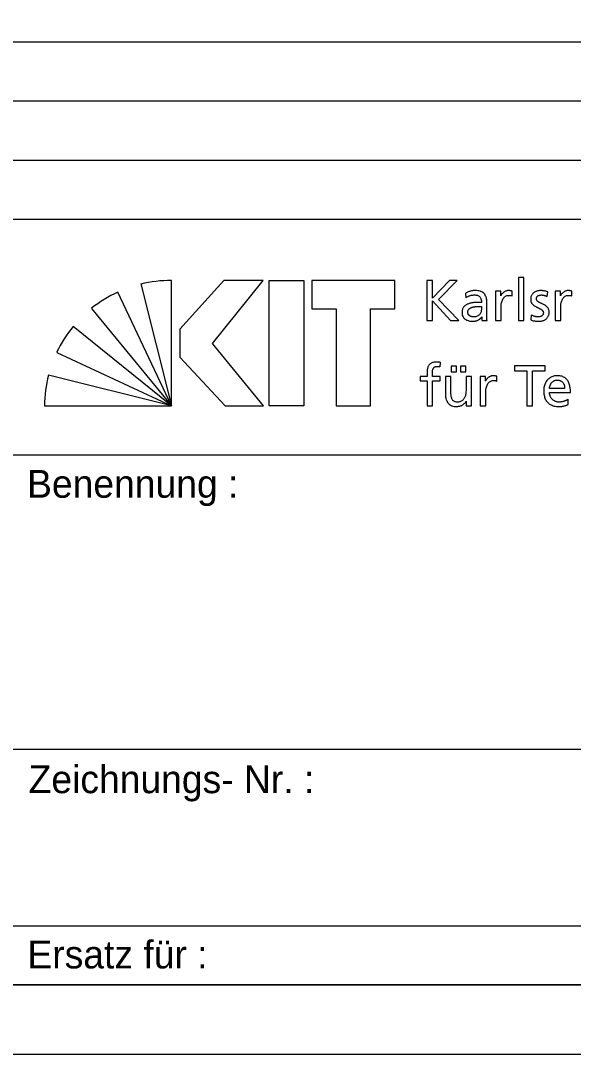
# Model space of a CAD drawing. Extents: x 0 to 168, y 0 to 119.
# Drawn here: x 150.53 to 158.47, y 0 to 14.85 of the extents above; entities that cross this region are included whole.
import ezdxf

# ---------------------------------------------------------------- set-up
doc = ezdxf.new("R2010")
doc.units = 0
doc.layers.add('90_Plankopf', color=7, linetype='Continuous')

msp = doc.modelspace()

# ---------------------------------------------------------------- linework, layer by layer
at = {"layer": '90_Plankopf'}
for p, q in [((131.624, 14.548), (167.2, 14.548)), ((131.624, 13.698), (167.2, 13.698)), ((131.624, 12.848), (167.2, 12.848)), ((131.624, 11.998), (167.2, 11.998)), ((131.624, 11.998), (167.2, 11.998)), ((152.255, 11.067), (152.696, 9.317)), ((152.696, 9.317), (152.696, 11.117)), ((156.362, 11.117), (156.362, 10.541)), ((152.696, 9.317), (151.927, 10.95)), ((156.916, 10.932), (156.92, 10.866)), ((157.585, 10.897), (157.585, 10.966)), ((158.091, 10.888), (158.098, 10.956)), ((158.442, 10.897), (158.442, 10.966)), ((151.549, 10.717), (152.696, 9.317)), ((157.146, 10.742), (157.146, 10.705)), ((157.224, 10.624), (157.224, 10.798)), ((157.859, 10.624), (157.855, 10.554)), ((152.696, 9.317), (151.287, 10.457)), ((156.362, 10.541), (156.444, 10.541)), ((156.701, 10.541), (156.822, 10.541)), ((151.048, 10.083), (152.696, 9.317)), ((156.555, 9.879), (156.558, 9.941)), ((152.696, 9.317), (150.932, 9.758)), ((157.365, 9.673), (157.365, 9.742)), ((158.341, 9.568), (158.123, 9.568)), ((158.123, 9.51), (158.424, 9.51)), ((158.392, 9.335), (158.392, 9.412)), ((150.873, 9.317), (152.696, 9.317)), ((150.4, 8.614), (167.2, 8.614)), ((150.4, 4.384), (167.2, 4.384)), ((150.4, 1.846), (167.2, 1.846)), ((167.2, 1), (131.624, 1)), ((133.96, 1), (167.2, 1)), ((133.96, 1), (167.2, 1))]:
    msp.add_line(p, q, dxfattribs=at)
for points in [[(0, 0), (168.2, 0), (168.2, 118.8), (0, 118.8)], [(5, 117.8), (167.2, 117.8), (167.2, 1), (5, 1)], [(154.013, 11.117), (153.447, 11.117), (152.815, 10.42), (152.815, 10.018), (153.468, 9.317), (154.017, 9.317), (153.284, 10.213)], [(154.594, 11.117), (154.594, 9.317), (154.1, 9.317), (154.1, 11.117)], [(154.712, 11.117), (154.712, 10.712), (155.06, 10.712), (155.06, 9.317), (155.554, 9.317), (155.554, 10.712), (155.902, 10.712), (155.902, 11.117)]]:
    msp.add_lwpolyline(points, close=True, dxfattribs=at)
for points in [[(157.676, 10.541), (157.754, 10.541), (157.754, 11.16), (157.676, 11.16), (157.676, 10.541)], [(156.822, 10.541), (156.529, 10.845), (156.8, 11.117), (156.69, 11.117), (156.444, 10.864), (156.444, 11.117), (156.362, 11.117)], [(157.424, 10.897), (157.423, 10.897), (157.423, 10.962), (157.35, 10.962), (157.35, 10.541), (157.428, 10.541), (157.428, 10.733)], [(158.281, 10.897), (158.28, 10.897), (158.28, 10.962), (158.207, 10.962), (158.207, 10.541), (158.285, 10.541), (158.285, 10.733)], [(156.444, 10.541), (156.444, 10.823), (156.701, 10.541)], [(157.153, 10.596), (157.154, 10.596), (157.154, 10.541), (157.227, 10.541)], [(156.711, 9.885), (156.711, 9.803), (156.788, 9.803), (156.788, 9.885), (156.711, 9.885)], [(156.846, 9.885), (156.846, 9.803), (156.924, 9.803), (156.924, 9.885), (156.846, 9.885)], [(157.798, 9.317), (157.881, 9.317), (157.881, 9.821), (158.06, 9.821), (158.06, 9.893), (157.619, 9.893), (157.619, 9.821), (157.798, 9.821), (157.798, 9.317)], [(156.365, 9.777), (156.365, 9.738), (156.266, 9.738), (156.266, 9.676), (156.365, 9.676), (156.365, 9.317), (156.442, 9.317), (156.442, 9.676), (156.554, 9.676), (156.554, 9.738), (156.442, 9.738), (156.442, 9.784)], [(156.708, 9.52), (156.708, 9.738), (156.631, 9.738), (156.631, 9.488)], [(157.003, 9.317), (157.003, 9.738), (156.925, 9.738), (156.925, 9.543)], [(157.204, 9.673), (157.203, 9.673), (157.203, 9.738), (157.13, 9.738), (157.13, 9.317), (157.208, 9.317), (157.208, 9.509)], [(156.926, 9.384), (156.928, 9.384), (156.928, 9.317), (157.003, 9.317)]]:
    msp.add_lwpolyline(points, dxfattribs=at)
for centre, start, end in [((152.69, 9.211), 89.8053, 103.1895), ((152.732, 9.224), 115.0126, 128.3968), ((152.763, 9.253), 140.7898, 154.174), ((152.778, 9.288), 165.7222, 179.1064)]:
    msp.add_arc(centre, 1.906, start, end, dxfattribs=at)
for points in [[(157.224, 10.798), (157.224, 10.836), (157.218, 10.868), (157.207, 10.894), (157.195, 10.92), (157.177, 10.939), (157.152, 10.952), (157.127, 10.965), (157.094, 10.972), (157.054, 10.972), (157.028, 10.972), (157.003, 10.968), (156.98, 10.961), (156.956, 10.954), (156.935, 10.944), (156.916, 10.932)], [(156.92, 10.866), (156.931, 10.875), (156.943, 10.883), (156.956, 10.889), (156.969, 10.896), (156.983, 10.901), (156.998, 10.904), (157.013, 10.908), (157.027, 10.909), (157.042, 10.909), (157.068, 10.909), (157.088, 10.905), (157.104, 10.897), (157.119, 10.889), (157.13, 10.877), (157.136, 10.86), (157.143, 10.844), (157.146, 10.824), (157.146, 10.799)], [(157.585, 10.966), (157.58, 10.967), (157.575, 10.968), (157.57, 10.969), (157.565, 10.97), (157.56, 10.971), (157.554, 10.971), (157.548, 10.972), (157.542, 10.972), (157.534, 10.972), (157.519, 10.972), (157.505, 10.969), (157.49, 10.962), (157.476, 10.956), (157.464, 10.947), (157.452, 10.936), (157.441, 10.925), (157.431, 10.912), (157.424, 10.897)], [(157.428, 10.733), (157.428, 10.768), (157.433, 10.799), (157.442, 10.824), (157.451, 10.85), (157.465, 10.87), (157.482, 10.883), (157.499, 10.897), (157.519, 10.904), (157.542, 10.904), (157.549, 10.904), (157.556, 10.904), (157.564, 10.903), (157.571, 10.902), (157.578, 10.9), (157.585, 10.897)], [(158.098, 10.956), (158.083, 10.96), (158.067, 10.964), (158.052, 10.967), (158.036, 10.97), (158.019, 10.972), (158.001, 10.972), (157.981, 10.972), (157.961, 10.969), (157.943, 10.964), (157.925, 10.959), (157.909, 10.951), (157.896, 10.94), (157.882, 10.929), (157.872, 10.916), (157.864, 10.9), (157.857, 10.883), (157.853, 10.864), (157.853, 10.842), (157.853, 10.826), (157.856, 10.811), (157.863, 10.799), (157.869, 10.787), (157.878, 10.776), (157.889, 10.767), (157.9, 10.758), (157.912, 10.75), (157.925, 10.743), (157.938, 10.736), (157.951, 10.729), (157.963, 10.723), (157.976, 10.717), (157.988, 10.711), (157.999, 10.704), (158.01, 10.698), (158.019, 10.691), (158.025, 10.683), (158.032, 10.675), (158.035, 10.665), (158.035, 10.654), (158.035, 10.643), (158.033, 10.633), (158.028, 10.626), (158.023, 10.618), (158.017, 10.612), (158.009, 10.607), (158.001, 10.602), (157.993, 10.599), (157.983, 10.597), (157.974, 10.595), (157.965, 10.594), (157.956, 10.594), (157.948, 10.594), (157.939, 10.595), (157.928, 10.597), (157.917, 10.599), (157.905, 10.603), (157.893, 10.607), (157.881, 10.612), (157.87, 10.617), (157.859, 10.624)], [(157.855, 10.554), (157.873, 10.545), (157.892, 10.539), (157.912, 10.536), (157.931, 10.532), (157.951, 10.531), (157.971, 10.531), (157.99, 10.531), (158.008, 10.534), (158.025, 10.539), (158.043, 10.544), (158.059, 10.552), (158.073, 10.563), (158.086, 10.574), (158.097, 10.588), (158.105, 10.604), (158.114, 10.621), (158.118, 10.64), (158.118, 10.662), (158.118, 10.682), (158.114, 10.698), (158.108, 10.711), (158.101, 10.724), (158.092, 10.736), (158.082, 10.745), (158.071, 10.754), (158.059, 10.762), (158.046, 10.769), (158.033, 10.776), (158.02, 10.782), (158.007, 10.787), (157.994, 10.793), (157.982, 10.799), (157.972, 10.805), (157.961, 10.812), (157.952, 10.819), (157.945, 10.827), (157.939, 10.836), (157.936, 10.846), (157.935, 10.858), (157.936, 10.87), (157.939, 10.879), (157.946, 10.887), (157.953, 10.894), (157.962, 10.9), (157.973, 10.904), (157.984, 10.908), (157.996, 10.909), (158.01, 10.909), (158.014, 10.909), (158.02, 10.909), (158.028, 10.908), (158.035, 10.906), (158.043, 10.905), (158.051, 10.903), (158.059, 10.901), (158.067, 10.898), (158.074, 10.896), (158.081, 10.893), (158.087, 10.891), (158.091, 10.888)], [(158.442, 10.966), (158.437, 10.967), (158.432, 10.968), (158.427, 10.969), (158.422, 10.97), (158.417, 10.971), (158.411, 10.971), (158.405, 10.972), (158.399, 10.972), (158.391, 10.972), (158.376, 10.972), (158.362, 10.969), (158.347, 10.962), (158.333, 10.956), (158.321, 10.947), (158.309, 10.936), (158.298, 10.925), (158.288, 10.912), (158.281, 10.897)], [(158.285, 10.733), (158.285, 10.768), (158.29, 10.799), (158.299, 10.824), (158.308, 10.85), (158.322, 10.87), (158.339, 10.883), (158.356, 10.897), (158.376, 10.904), (158.399, 10.904), (158.406, 10.904), (158.413, 10.904), (158.421, 10.903), (158.428, 10.902), (158.435, 10.9), (158.442, 10.897)], [(157.146, 10.799), (157.136, 10.8), (157.127, 10.8), (157.118, 10.801), (157.109, 10.801), (157.1, 10.801), (157.092, 10.801), (157.083, 10.801), (157.074, 10.801), (157.064, 10.801), (157.047, 10.801), (157.03, 10.8), (157.013, 10.797), (156.995, 10.794), (156.977, 10.789), (156.96, 10.783), (156.943, 10.776), (156.928, 10.768), (156.914, 10.757), (156.9, 10.746), (156.889, 10.733), (156.881, 10.718), (156.872, 10.702), (156.868, 10.684), (156.868, 10.662), (156.868, 10.632), (156.875, 10.607), (156.888, 10.588), (156.901, 10.568), (156.919, 10.554), (156.942, 10.545), (156.965, 10.536), (156.992, 10.531), (157.022, 10.531), (157.04, 10.531), (157.056, 10.534), (157.07, 10.538), (157.084, 10.542), (157.097, 10.547), (157.107, 10.554), (157.118, 10.56), (157.127, 10.567), (157.135, 10.575), (157.142, 10.582), (157.148, 10.589), (157.153, 10.596)], [(157.146, 10.705), (157.146, 10.684), (157.142, 10.665), (157.133, 10.648), (157.124, 10.631), (157.111, 10.618), (157.093, 10.609), (157.076, 10.599), (157.054, 10.594), (157.029, 10.594), (157.02, 10.594), (157.011, 10.596), (157.002, 10.598), (156.993, 10.601), (156.984, 10.606), (156.976, 10.611), (156.969, 10.617), (156.962, 10.625), (156.958, 10.633), (156.953, 10.641), (156.951, 10.651), (156.95, 10.662), (156.951, 10.677), (156.954, 10.69), (156.962, 10.699), (156.969, 10.709), (156.978, 10.717), (156.99, 10.723), (157.001, 10.729), (157.014, 10.733), (157.027, 10.736), (157.04, 10.739), (157.053, 10.741), (157.065, 10.742), (157.077, 10.743), (157.088, 10.743), (157.097, 10.743), (157.105, 10.743), (157.113, 10.743), (157.121, 10.743), (157.13, 10.742), (157.138, 10.742), (157.146, 10.742)], [(157.227, 10.541), (157.226, 10.545), (157.226, 10.551), (157.225, 10.557), (157.225, 10.564), (157.224, 10.573), (157.224, 10.584), (157.224, 10.595), (157.224, 10.608), (157.224, 10.624)], [(156.558, 9.941), (156.55, 9.942), (156.542, 9.944), (156.534, 9.945), (156.525, 9.946), (156.516, 9.946), (156.506, 9.946), (156.478, 9.946), (156.454, 9.942), (156.436, 9.934), (156.417, 9.926), (156.403, 9.915), (156.392, 9.9), (156.382, 9.885), (156.375, 9.867), (156.371, 9.847), (156.367, 9.826), (156.365, 9.803), (156.365, 9.777)], [(156.442, 9.784), (156.442, 9.798), (156.443, 9.811), (156.445, 9.823), (156.446, 9.835), (156.45, 9.846), (156.455, 9.855), (156.46, 9.864), (156.468, 9.871), (156.478, 9.876), (156.488, 9.881), (156.501, 9.883), (156.518, 9.883), (156.524, 9.883), (156.531, 9.883), (156.538, 9.882), (156.544, 9.881), (156.55, 9.88), (156.555, 9.879)], [(157.365, 9.742), (157.36, 9.743), (157.355, 9.744), (157.35, 9.745), (157.345, 9.746), (157.34, 9.747), (157.334, 9.747), (157.328, 9.748), (157.322, 9.748), (157.314, 9.748), (157.299, 9.748), (157.285, 9.745), (157.27, 9.738), (157.256, 9.732), (157.244, 9.723), (157.232, 9.712), (157.221, 9.701), (157.211, 9.688), (157.204, 9.673)], [(157.208, 9.509), (157.208, 9.544), (157.213, 9.575), (157.222, 9.6), (157.232, 9.626), (157.245, 9.646), (157.262, 9.659), (157.279, 9.673), (157.299, 9.68), (157.322, 9.68), (157.329, 9.681), (157.336, 9.68), (157.344, 9.679), (157.351, 9.678), (157.358, 9.676), (157.365, 9.673)], [(158.424, 9.51), (158.424, 9.544), (158.421, 9.576), (158.414, 9.605), (158.408, 9.634), (158.398, 9.659), (158.384, 9.68), (158.369, 9.701), (158.35, 9.718), (158.326, 9.73), (158.302, 9.742), (158.273, 9.748), (158.238, 9.748), (158.208, 9.748), (158.181, 9.743), (158.157, 9.732), (158.133, 9.722), (158.112, 9.707), (158.095, 9.688), (158.077, 9.669), (158.064, 9.647), (158.055, 9.621), (158.046, 9.595), (158.041, 9.567), (158.041, 9.535), (158.041, 9.501), (158.045, 9.47), (158.054, 9.442), (158.062, 9.414), (158.076, 9.39), (158.094, 9.37), (158.112, 9.35), (158.134, 9.334), (158.162, 9.324), (158.189, 9.313), (158.221, 9.308), (158.259, 9.307), (158.282, 9.308), (158.301, 9.309), (158.317, 9.312), (158.333, 9.315), (158.347, 9.319), (158.359, 9.323), (158.371, 9.327), (158.382, 9.331), (158.392, 9.335)], [(158.123, 9.568), (158.125, 9.582), (158.128, 9.596), (158.133, 9.609), (158.138, 9.623), (158.144, 9.636), (158.154, 9.647), (158.162, 9.659), (158.174, 9.668), (158.187, 9.675), (158.201, 9.682), (158.217, 9.685), (158.236, 9.685), (158.253, 9.685), (158.268, 9.682), (158.281, 9.676), (158.294, 9.67), (158.305, 9.662), (158.314, 9.651), (158.323, 9.64), (158.33, 9.628), (158.334, 9.614), (158.339, 9.6), (158.341, 9.584), (158.341, 9.568)], [(156.925, 9.543), (156.925, 9.518), (156.923, 9.494), (156.918, 9.473), (156.913, 9.452), (156.905, 9.434), (156.895, 9.418), (156.884, 9.403), (156.871, 9.391), (156.855, 9.383), (156.839, 9.374), (156.819, 9.37), (156.797, 9.37), (156.775, 9.371), (156.757, 9.378), (156.744, 9.389), (156.731, 9.4), (156.722, 9.417), (156.716, 9.439), (156.711, 9.46), (156.708, 9.488), (156.708, 9.52)], [(158.392, 9.412), (158.387, 9.408), (158.38, 9.404), (158.37, 9.399), (158.361, 9.394), (158.351, 9.39), (158.339, 9.385), (158.327, 9.381), (158.314, 9.377), (158.301, 9.374), (158.288, 9.372), (158.275, 9.37), (158.262, 9.37), (158.243, 9.37), (158.226, 9.374), (158.209, 9.38), (158.193, 9.387), (158.178, 9.397), (158.165, 9.409), (158.152, 9.421), (158.142, 9.436), (158.135, 9.453), (158.127, 9.471), (158.123, 9.49), (158.123, 9.51)], [(156.631, 9.488), (156.631, 9.45), (156.636, 9.418), (156.647, 9.391), (156.659, 9.364), (156.676, 9.343), (156.699, 9.329), (156.722, 9.315), (156.752, 9.308), (156.788, 9.307), (156.808, 9.308), (156.827, 9.311), (156.845, 9.317), (156.863, 9.323), (156.879, 9.332), (156.893, 9.343), (156.907, 9.354), (156.918, 9.368), (156.926, 9.384)]]:
    msp.add_open_spline(points, degree=3, dxfattribs=at)

# ---------------------------------------------------------------- texts
for s, p in [('Benennung :', (150.623, 7.996)), ('Zeichnungs- Nr. :', (150.645, 3.752)), ('Ersatz für :', (150.628, 1.234))]:
    msp.add_text(s, height=0.4, dxfattribs=at).set_placement(p)

doc.saveas('drawing.dxf')
